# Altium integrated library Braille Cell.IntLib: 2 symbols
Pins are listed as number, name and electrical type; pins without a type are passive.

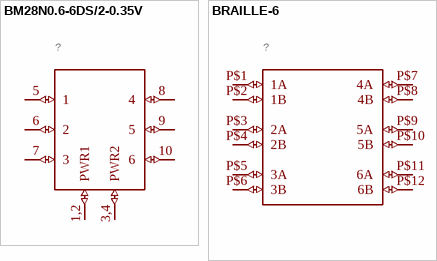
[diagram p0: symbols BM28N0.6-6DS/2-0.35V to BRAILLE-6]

## BM28N0.6-6DS/2-0.35V
designator ?
GateName_1: G$1; SymbolName_1: BM28N0.6-6DS/2-0.35V
footprint BM28N0.6-6DS/2-0.35V
pins: 1,2 PWR1 (io), 3,4 PWR2 (io), 5 1 (io), 6 2 (io), 7 3 (io), 8 4 (io), 9 5 (io), 10 6 (io)

## BRAILLE-6
designator ?
GateName_1: G$1; SymbolName_1: BRAILLE-6
footprint BRAILLE-6
pins: P$1 1A (io), P$2 1B (io), P$3 2A (io), P$4 2B (io), P$5 3A (io), P$6 3B (io), P$7 4A (io), P$8 4B (io), P$9 5A (io), P$10 5B (io), P$11 6A (io), P$12 6B (io)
